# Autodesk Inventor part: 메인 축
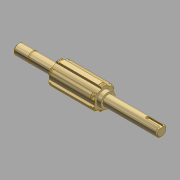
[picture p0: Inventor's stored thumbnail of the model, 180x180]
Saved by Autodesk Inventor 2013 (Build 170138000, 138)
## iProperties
Created: 2015-11
Part Number: 메인 축
Document SubType Name: 모델링
Designer: mdu
Mass: 21.4461 g
Surface Area: 72.5104 cm^2
Volume: 21.4461 cm^3
Density: 1 g/cm^3
Material: 일반
변환 표준: STEP AP214IS
파일 이름: C:\Users\SeoGD\Desktop\?쒗뿕\硫붿씤 異?.stp
전처리기: Build: 253, Release: 2010 SP1 - Date: Wed 07/29/2009
전송 단위: 밀리미터
불확실성: 0.01
Author: mdu
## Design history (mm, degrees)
sketch "스케치1"
  geometry: L1 (-69.5, 0)-(69.5, 0); L2 (69.5, 0)-(69.5, 5); L3 (69.5, 5)-(55.5, 5); L4 (55.5, 5)-(55.5, 4.8); L5 (55.5, 4.8)-(54.35, 4.8); L6 (54.35, 4.8)-(54.35, 5); L7 (54.35, 5)-(30.5, 5); L8 (30.5, 5)-(30.5, 9); L9 (30.5, 9)-(-13.5, 9); L10 (-13.5, 9)-(-13.5, 7); L11 (-13.5, 7)-(-17.5, 7); L12 (-17.5, 7)-(-17.5, 5); L13 (-17.5, 5)-(-69.5, 5); L14 (-69.5, 5)-(-69.5, 0); 2 further points
  constraints: 28 end point, 9 parallel, 4 collinear, 2 perpendicular, 1 coincident, 1 horizontal, 1 midpoint
  dimensions: "d2" = 1.15 distance between parallel lines of L6 L4; "d3" = 10 diameter of L3 L1; "d4" = 9.6 diameter of L5 L1; "d6" = 44 distance between parallel lines of L10 L8; "d7" = 4 distance between parallel lines of L12 L10; "d8" = 14 diameter of L11 L1; "d9" = 18 diameter of L9 L1; "d33" = 52 distance from line of L12.end L14; "d37" = 39 distance between parallel lines of L8 L2; "d38" = 14 distance between parallel lines of L2 L4
revolve "회전1" sketch "스케치1" stored, may be unused: angle "d10" = 90 deg
sketch "스케치2"
  geometry: L1 (2.5, 10.712)-(2.5, 8.646); L2 (-2.5, 10.712)-(-2.5, 8.646); A1 r 9 centre (0, 0) between (2.5, 8.646) and (-2.5, 8.646) reference; A2 r 11 centre (0, 0) between (2.5, 10.712) and (-2.5, 10.712); 1 further point
  constraints: 4 end point, 4 point on circle, 2 parallel, 1 centre point, 1 coincident, 1 vertical
  dimensions: "d11" = 22 diameter of A2; "d12" = 5 distance between parallel lines of L1 L2
extrude "돌출1" join sketch "스케치2" stored distance "d13" = 10; taper "d14" = 0 deg
chamfer "모따기1" distance "d15" = 1; stored, may be unused: second distance "d16" = 2, angle "d17" = 45 deg
node "작업 평면1"
node "작업 평면2"
sketch "스케치3"
  geometry: L1 (2.5, 10.712)-(2.5, 10.198); L2 (-2.5, 10.712)-(-2.5, 10.198); A1 r 11 centre (0, 0) between (2.5, 10.712) and (-2.5, 10.712) reference; A2 r 10.5 centre (0, 0) between (2.5, 10.198) and (-2.5, 10.198); 1 further point
  constraints: 4 end point, 2 point on circle, 1 centre point, 1 coincident, 1 parallel, 1 vertical
  dimensions: "d19" = 21 diameter of A2
extrude "돌출2" cut sketch "스케치3" distance "d20" = 1.35; taper "d21" = 0 deg
node "작업 평면3"
sketch "스케치4"
  geometry: L1 (-26, -5)-(-26, 5) reference; L2 (-26, 1.5)-(-12.5, 1.5); L3 (-12.5, -1.5)-(-26, -1.5); A1 r 1.5 centre (-12.5, 0) between (-12.5, -1.5) and (-12.5, 1.5); 2 further points
  constraints: 4 end point, 2 perpendicular, 2 point on circle, 2 point on line, 2 tangent, 1 centre point, 1 horizontal alignment, 1 midpoint
  dimensions: "d25" = 3 distance between parallel lines of L3 L2; "d26" = 15 dimension on A1 L1
extrude "돌출3" cut sketch "스케치4" distance "d27" = 1.8; taper "d28" = 0 deg
chamfer "모따기2" distance "d29" = 1; stored, may be unused: second distance "d30" = 2, angle "d31" = 45 deg
node "솔리드1"
node "솔리드 본체"
node "곡면 본체"
mirror "대칭1"
pattern_circular "원형 패턴1" dims "d23" = 360 deg
node "솔리드2"
other parameters: "d18" = -1.65
